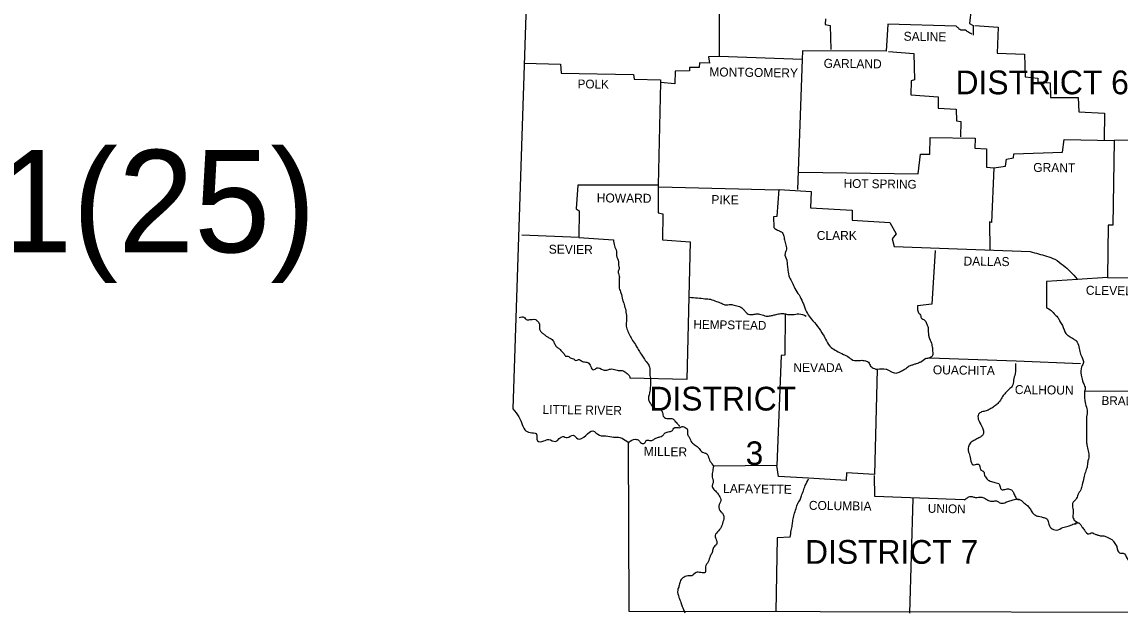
# Model space of a CAD drawing. Extents: x -549 to 3324, y -742 to 2142.
# Drawn here: x 2237 to 2752, y 1337 to 1615 of the extents above; entities that cross this region are included whole.
import ezdxf

# ---------------------------------------------------------------- set-up
doc = ezdxf.new("R2010")
doc.units = 0
for name, color, linetype in [('1', 7, 'Continuous'), ('2', 7, 'Continuous'), ('3', 7, 'Continuous')]:
    doc.layers.add(name, color=color, linetype=linetype)

msp = doc.modelspace()

# ---------------------------------------------------------------- linework, layer by layer
at = {"layer": '1'}
for points in [[(2455.88, 1861.21), (2476.13, 1698.6), (2467.33, 1433.16)], [(2564.19, 1655.65), (2563.99, 1598.41), (2559.1, 1598.32), (2559.49, 1595.38), (2554.8, 1595.48), (2554.7, 1593.33), (2550.1, 1593.33), (2550.2, 1591.76), (2543.35, 1591.57), (2543.25, 1585.6), (2536.6, 1586.18), (2535.52, 1538.05), (2497.85, 1538.14), (2496.97, 1526.99), (2498.34, 1526.01), (2498.24, 1513.49), (2471.53, 1514.66)], [(2714.08, 1627.57), (2707.04, 1628.35), (2707.33, 1625.71), (2694.51, 1625.22), (2694.12, 1621.41), (2682.09, 1620.72), (2681.4, 1613.87), (2683.16, 1612.99), (2683.16, 1608.49)], [(2675.14, 1612.6), (2643.15, 1613.58), (2642.26, 1600.96), (2603.13, 1601.15), (2602.93, 1596.95)], [(2613.89, 1616.03), (2613.79, 1613.38), (2616.04, 1612.99), (2616.43, 1601.64)], [(2683.85, 1612.9), (2694.81, 1612.21), (2694.41, 1599.98), (2707.23, 1599.49), (2707.43, 1588.83), (2713.49, 1588.34), (2713.49, 1586.48), (2719.17, 1586.09), (2719.36, 1579.24), (2732.28, 1579.24), (2732.67, 1572.49), (2744.61, 1571.9), (2744.51, 1559.18)], [(2602.93, 1596.95), (2563.99, 1598.41)], [(2602.93, 1596.95), (2600.68, 1535.99)], [(2643.44, 1600.76), (2655.28, 1599.88), (2655.67, 1587.55), (2654.01, 1586.97), (2653.81, 1580.41), (2666.63, 1579.53), (2666.63, 1574.15), (2675.14, 1573.66), (2675.24, 1568.28), (2677.29, 1567.99), (2677.19, 1560.75)], [(2472.71, 1595.38), (2489.63, 1594.79), (2490.02, 1590.69), (2523.88, 1590), (2524.27, 1587.85), (2536.6, 1587.46), (2536.5, 1585.6)], [(2861.23, 1570.43), (2824.25, 1571.41), (2824.05, 1559.38), (2749.2, 1559.08)], [(2601.37, 1544.11), (2657.33, 1543.33), (2658.41, 1552.63), (2662.81, 1552.63), (2662.91, 1560.45), (2684.04, 1560.16), (2683.85, 1555.46), (2689.33, 1555.07), (2689.33, 1546.46), (2692.85, 1546.17)], [(2692.85, 1546.17), (2698.33, 1546.95), (2698.72, 1550.28), (2701.95, 1550.86), (2702.14, 1552.82), (2724.94, 1553.51), (2725.82, 1559.47), (2749.2, 1559.08)], [(2749.2, 1558.89), (2748.62, 1519.36), (2746.37, 1519.26), (2746.07, 1494.7)], [(2692.85, 1546.17), (2691.67, 1520.53), (2690.79, 1520.83), (2690.89, 1507.52)], [(2535.52, 1538.05), (2535.52, 1525.03), (2537.67, 1524.64), (2537.48, 1512.51), (2550.39, 1511.53), (2548.83, 1446.86), (2522.21, 1447.54)], [(2535.72, 1537.36), (2591.68, 1535.89)], [(2589.82, 1517.99), (2589.63, 1523.37), (2591.19, 1523.47), (2592.17, 1536.09), (2607.24, 1535.11), (2606.85, 1527.38), (2626.32, 1526.31), (2626.41, 1521.61), (2644.03, 1520.53), (2647.06, 1515.25), (2645.2, 1512.9), (2646.08, 1509.28), (2709.87, 1506.93)], [(2498.24, 1513.49), (2514.48, 1512.51)], [(2665.26, 1507.42), (2663.79, 1482.28), (2657.04, 1481.5)], [(2731.98, 1493.82), (2717.5, 1492.94), (2717.41, 1480.71)], [(2746.07, 1494.7), (2731.79, 1493.82)], [(2746.07, 1494.7), (2780.71, 1494.51)], [(2595.01, 1477.78), (2594.81, 1458.31), (2593.05, 1458.11), (2591.09, 1406.55)], [(2662.81, 1457.13), (2703.32, 1455.67), (2733.35, 1454.49)], [(2638.16, 1451.65), (2636.88, 1402.34), (2623.67, 1403.22), (2623.58, 1399.6), (2605.97, 1400.68)], [(2735.31, 1441.48), (2779.54, 1441.58)], [(2521.43, 1417.41), (2521.63, 1338.26), (2880.21, 1337.67)], [(2605.97, 1400.68), (2591.78, 1401.46), (2591.09, 1406.55), (2561.45, 1406.26)], [(2678.86, 1390.41), (2637.08, 1391.97), (2636.88, 1401.85)], [(2654.89, 1391.09), (2653.32, 1337.38)], [(2597.36, 1372.99), (2591.29, 1372.6), (2590.6, 1338.16)]]:
    msp.add_lwpolyline(points, dxfattribs=at)
for points in [[(2682.48, 1608.98), (2680.62, 1609.96), (2679.15, 1610.84), (2677.59, 1610.74), (2676.31, 1611.53), (2675.14, 1612.6)], [(2589.82, 1517.99), (2591.39, 1517.01), (2593.25, 1516.13), (2594.22, 1514.66), (2594.62, 1512.41), (2595.3, 1509.97), (2595.5, 1507.42), (2594.91, 1506.05), (2595.69, 1502.92), (2595.99, 1500.77), (2596.28, 1498.23), (2597.06, 1494.8), (2598.33, 1492.45), (2599.51, 1489.62), (2601.47, 1486.58), (2603.13, 1483.26), (2603.91, 1481.5), (2605.38, 1477.87), (2607.24, 1475.43), (2610.17, 1471.71), (2612.81, 1467.9), (2614.28, 1465.06), (2616.53, 1461.93), (2619.08, 1460.36), (2622.31, 1458.7), (2624.36, 1457.72), (2626.71, 1456.06), (2629.74, 1455.86), (2631.99, 1455.86), (2634.05, 1454.98), (2635.02, 1453.22), (2636.79, 1452.05), (2638.16, 1451.65)], [(2514.48, 1512.51), (2514.97, 1509.58), (2515.85, 1507.03), (2515.95, 1505.07), (2516.83, 1502.14), (2516.83, 1501.06), (2517.13, 1498.91), (2516.74, 1497.74), (2517.22, 1495.39), (2517.13, 1493.63), (2517.13, 1492.16), (2517.22, 1489.71), (2518.01, 1487.56), (2518.79, 1484.33), (2519.28, 1482.67), (2520.06, 1480.13), (2520.55, 1476.99), (2520.65, 1474.65), (2520.45, 1472.49), (2521.04, 1470.05), (2522.12, 1467.6), (2523.49, 1465.25), (2525.15, 1462.61), (2526.32, 1460.56), (2527.79, 1458.31), (2528.97, 1456.45), (2530.73, 1454.1), (2531.51, 1452.14), (2531.51, 1449.4), (2531.9, 1446.86), (2531.8, 1444.02), (2531.61, 1441.48), (2530.92, 1437.96), (2531.41, 1436.29), (2533.27, 1433.85), (2534.44, 1433.16), (2536.5, 1432.77), (2537.48, 1431.4), (2538.06, 1429.35), (2540.12, 1428.66), (2542.37, 1428.47), (2543.45, 1427.29), (2544.91, 1425.73), (2545.4, 1424.94)], [(2709.87, 1506.93), (2717.5, 1504.78), (2721.42, 1503.31), (2725.33, 1500.48), (2728.56, 1497.64), (2731.79, 1494.02)], [(2550.2, 1485.51), (2553.91, 1485.21), (2557.34, 1484.82), (2559.98, 1484.53), (2562.72, 1483.55), (2565.17, 1482.67), (2566.73, 1481.98), (2569.37, 1482.18), (2571.62, 1481.69), (2574.17, 1480.81), (2576.03, 1479.15), (2577.2, 1477.87), (2579.45, 1477.39), (2581.31, 1477.68), (2583.56, 1477.48), (2586.1, 1476.7), (2588.16, 1476.8), (2589.82, 1477.19), (2591.78, 1477.68), (2594.22, 1477.87), (2596.08, 1477.48), (2598.53, 1477.39), (2601.37, 1477.68), (2604.89, 1476.7)], [(2657.04, 1481.5), (2657.04, 1479.64), (2657.72, 1477.87), (2658.41, 1477.09), (2658.7, 1475.82), (2659.58, 1475.23), (2660.85, 1474.06), (2661.54, 1472.4), (2662.03, 1471.32), (2662.03, 1469.95), (2662.13, 1468.58), (2662.32, 1466.92), (2663.5, 1463.98), (2663.79, 1462.81), (2663.99, 1461.83), (2664.08, 1460.17), (2664.08, 1458.21), (2662.81, 1457.13)], [(2717.41, 1480.71), (2719.66, 1479.24), (2721.52, 1477.29), (2722.89, 1475.82), (2723.77, 1474.16), (2724.94, 1472.2), (2726.6, 1468.48), (2728.07, 1467.21), (2730.13, 1465.94), (2731.4, 1465.06), (2732.67, 1462.22), (2733.26, 1459.38), (2734.33, 1456.84), (2734.82, 1454.88), (2733.94, 1452.93), (2733.75, 1449.01), (2734.33, 1446.37), (2735.12, 1444.41), (2735.6, 1442.16), (2735.31, 1441.48)], [(2470.36, 1476.02), (2472.51, 1476.11), (2473.98, 1474.84), (2474.86, 1474.94), (2476.42, 1475.14), (2477.89, 1475.04), (2478.97, 1474.16), (2479.85, 1472.59), (2479.75, 1471.12), (2479.85, 1470.54), (2480.53, 1469.26), (2481.71, 1468.29), (2482.98, 1467.31), (2484.15, 1466.53), (2486.11, 1465.25), (2486.31, 1464.86), (2487.09, 1463.3), (2488.07, 1462.02), (2489.24, 1461.24), (2490.51, 1459.87), (2491.1, 1459.29), (2492.08, 1457.92), (2493.16, 1457.82), (2494.62, 1456.94), (2495.7, 1456.64), (2496.87, 1455.86), (2498.05, 1456.25), (2499.52, 1455.67), (2501.47, 1455.08), (2502.55, 1454.88), (2503.82, 1453.02), (2505.09, 1451.46), (2506.66, 1452.34), (2509.59, 1451.46), (2511.45, 1451.36), (2513.11, 1451.85), (2514.39, 1451.75), (2516.74, 1451.16), (2518.2, 1451.16), (2519.77, 1450.58), (2521.24, 1449.4), (2522.21, 1448.13), (2522.21, 1447.54)], [(2660.95, 1456.74), (2658.41, 1455.08), (2656.45, 1454.3), (2654.98, 1453.81), (2653.61, 1453.41), (2651.85, 1452.24), (2650.48, 1451.26), (2648.62, 1450.38), (2646.86, 1449.79), (2644.71, 1450.48), (2643.54, 1451.16), (2642.26, 1451.65), (2638.16, 1451.65)], [(2658.41, 1455.08), (2660.95, 1456.74), (2662.81, 1457.13)], [(2702.93, 1454.49), (2702.73, 1449.6), (2702.05, 1446.57), (2701.36, 1443.83), (2699.89, 1442.26), (2698.33, 1440.7), (2696.86, 1438.93), (2695.59, 1436.78), (2694.32, 1435.41), (2692.65, 1434.04), (2690.99, 1433.06), (2689.13, 1432.18), (2687.08, 1431.69), (2685.61, 1430.62), (2685.51, 1428.27), (2687.17, 1424.94), (2687.76, 1423.38), (2687.96, 1421.52), (2687.27, 1420.44), (2685.71, 1419.56), (2683.85, 1418.49), (2682.18, 1417.51), (2681.01, 1415.84), (2680.81, 1413.59), (2681.6, 1410.95), (2681.89, 1409.39), (2683.16, 1406.94), (2684.14, 1407.04), (2685.9, 1406.94), (2686.1, 1406.45), (2686.2, 1405.96), (2686.59, 1404.69), (2688.05, 1403.61), (2688.25, 1402.64), (2689.13, 1400.78), (2690.6, 1399.5), (2691.67, 1399.11), (2693.92, 1398.43), (2695.1, 1398.13), (2696.37, 1395.3), (2697.94, 1395.4), (2699.11, 1395.59), (2701.07, 1395.1), (2701.95, 1393.93), (2702.83, 1391.97), (2704, 1390.6), (2704.78, 1390.6)], [(2735.31, 1441.48), (2735.7, 1435.41), (2736.58, 1432.48), (2736.29, 1429.35), (2736.19, 1426.31), (2736.19, 1423.57), (2736.19, 1420.93), (2736.19, 1418.19), (2736.39, 1416.24), (2737.07, 1413.4), (2737.37, 1410.76), (2736.78, 1408.21), (2736.49, 1405.86), (2735.7, 1403.52), (2735.02, 1400.87), (2734.23, 1397.45), (2733.55, 1395.2), (2732.18, 1392.85), (2731.3, 1390.7), (2729.93, 1389.33), (2729.73, 1386.98), (2730.03, 1384.83), (2729.83, 1382.87), (2730.52, 1381.01), (2732.28, 1379.74)], [(2467.33, 1433.16), (2470.16, 1429.44), (2471.34, 1426.8), (2473, 1423.38), (2475.45, 1422.01), (2478.28, 1421.52), (2478.87, 1418.19), (2481.81, 1418.09), (2484.15, 1418.78), (2487.38, 1417.9), (2490.81, 1420.25), (2492.76, 1419.66), (2495.6, 1420.83), (2497.75, 1419.07), (2501.47, 1420.64), (2504.8, 1422.79), (2507.93, 1420.74), (2510.96, 1420.44), (2514.58, 1419.95), (2517.42, 1419.76), (2519.96, 1418.49), (2521.82, 1417.21), (2521.43, 1417.41)], [(2521.43, 1417.41), (2524.86, 1418.88), (2526.32, 1418.39), (2527.6, 1417.12), (2529.06, 1417.12), (2529.85, 1418.29), (2531.31, 1418.39), (2532.49, 1418.29), (2533.76, 1419.07), (2534.84, 1419.56), (2536.3, 1420.05), (2537.38, 1420.44), (2538.36, 1421.52), (2540.12, 1422.4), (2542.17, 1423.08), (2542.76, 1424.06), (2543.74, 1424.45), (2545.7, 1424.36), (2546.97, 1424.94), (2548.04, 1424.45), (2549.02, 1423.77), (2549.22, 1421.23), (2550, 1419.86), (2551.17, 1417.41), (2552.84, 1416.14), (2554.4, 1414.87), (2554.99, 1414.08), (2556.65, 1412.62), (2558.12, 1412.13), (2558.81, 1411.05), (2559.88, 1408.51), (2561.45, 1406.26)], [(2561.45, 1406.26), (2560.86, 1403.42), (2560.76, 1401.17), (2561.25, 1398.53), (2560.76, 1397.25), (2561.55, 1395.4), (2563.01, 1393.93), (2564.09, 1392.36), (2564.77, 1390.11), (2563.89, 1387.57), (2564.87, 1384.93), (2565.75, 1383.95), (2566.24, 1382.38), (2565.56, 1379.35), (2564.68, 1377.1), (2562.72, 1374.85), (2562.13, 1373.77), (2562.43, 1372.3), (2562.92, 1369.96), (2562.43, 1369.27), (2561.15, 1367.61), (2560.76, 1365.75), (2559.88, 1364.18), (2558.9, 1361.35), (2557.63, 1359), (2557.44, 1356.36), (2555.48, 1356.36), (2553.23, 1356.36), (2551.17, 1354.89), (2549.32, 1354.79), (2547.07, 1353.91), (2545.7, 1352.05), (2545.21, 1350), (2544.62, 1348.04), (2545.21, 1344.71), (2546.09, 1342.37), (2546.77, 1340.51), (2547.95, 1337.47)], [(2597.36, 1372.99), (2597.84, 1376.12), (2598.33, 1378.57), (2598.63, 1380.91), (2599.21, 1383.56), (2600.1, 1386.39), (2600.88, 1388.74), (2601.95, 1390.41), (2602.64, 1392.36), (2603.52, 1394.71), (2604.4, 1397.16), (2605.97, 1400.29)], [(2678.86, 1390.41), (2680.42, 1391.48), (2681.89, 1392.07), (2683.36, 1391.78), (2684.92, 1391.58), (2686.29, 1391.78), (2688.05, 1391.48), (2689.52, 1390.6), (2691.18, 1389.92), (2692.85, 1389.92), (2694.32, 1389.92), (2695.59, 1389.04), (2697.94, 1389.13), (2699.89, 1389.92), (2701.85, 1390.5), (2704.49, 1390.8), (2706.84, 1389.13), (2708.5, 1387.76), (2709.87, 1386.2), (2710.85, 1384.44), (2711.93, 1383.46), (2713.69, 1382.77), (2715.06, 1382.48), (2716.72, 1381.99), (2717.6, 1381.6), (2718.38, 1379.74), (2719.66, 1377.2), (2722.1, 1376.32), (2725.14, 1377.49), (2727.58, 1378.18), (2729.34, 1378.76), (2730.42, 1379.15), (2731.4, 1379.25), (2731.1, 1379.45), (2732.28, 1379.74), (2733.35, 1378.96), (2734.04, 1377.88), (2735.21, 1376.32), (2736.29, 1374.95), (2737.37, 1374.46), (2738.44, 1375.04), (2739.91, 1374.56), (2741.18, 1374.07), (2742.65, 1373.67), (2743.92, 1373.58), (2745.58, 1373.19), (2746.86, 1372.5), (2748.03, 1371.82), (2749.2, 1370.54), (2750.38, 1368.59), (2750.77, 1367.02), (2752.14, 1365.46), (2753.41, 1365.46), (2755.27, 1362.91), (2755.96, 1361.93), (2757.42, 1360.17), (2758.5, 1360.17), (2760.55, 1359.78)]]:
    msp.add_spline(points, degree=3, dxfattribs=at)

# ---------------------------------------------------------------- texts
at = {"layer": '2'}
for s, height, rotation, p in [('SALINE', 4.207, 359.1491, (2650.48, 1605.85)), ('GARLAND', 4.207, 359.3658, (2613.01, 1593.13)), ('MONTGOMERY', 4.207, 359.2944, (2559.39, 1589.12)), ('POLK', 4.108, 359.2152, (2497.66, 1583.54)), ('GRANT', 4.207, 359.4032, (2711.24, 1544.31)), ('HOT SPRING', 4.109, 359.2216, (2622.4, 1536.87)), ('HOWARD', 4.207, 359.5145, (2506.66, 1530.02)), ('PIKE', 4.206, 359.0452, (2560.37, 1529.24)), ('SEVIER', 4.207, 359.4271, (2484.15, 1505.96)), ('DALLAS', 4.206, 359.2462, (2678.56, 1500.38)), ('CLEVELAND', 4.207, 359.3377, (2735.9, 1486.68)), ('HEMPSTEAD', 4.108, 359.1885, (2551.96, 1470.73)), ('OUACHITA', 4.207, 359.2043, (2664.18, 1449.4)), ('CALHOUN', 4.207, 359.3634, (2702.63, 1440.11)), ('BRADLEY', 4.108, 359.1449, (2743.24, 1435.02)), ('LITTLE RIVER', 4.2073, 359.1697, (2481.22, 1430.81)), ('MILLER', 4.206, 359.1319, (2528.67, 1411.15)), ('LAFAYETTE', 4.206, 359.1839, (2565.85, 1393.73)), ('COLUMBIA', 4.206, 359.2125, (2606.06, 1385.81)), ('UNION', 4.109, 358.9584, (2661.83, 1384.44))]:
    msp.add_text(s, height=height, rotation=rotation, dxfattribs=at).set_placement(p)
for s, height, p in [('FED.  AID PROJ.  STPF-0061(25)', 48, (1401.26, 1506.59)), ('CLARK', 4.207, (2609.8, 1512.39)), ('NEVADA', 4.207, (2598.82, 1450.38))]:
    msp.add_text(s, height=height, dxfattribs=at).set_placement(p)
at = {"layer": '3'}
for s, height, p in [('DISTRICT 6', 11.154, (2674.85, 1580.71)), ('DISTRICT', 11.154, (2531.36, 1432.37)), ('3', 11.06, (2576.47, 1406.83)), ('DISTRICT 7', 11.154, (2604.3, 1360.47))]:
    msp.add_text(s, height=height, dxfattribs=at).set_placement(p)

doc.saveas('drawing.dxf')
